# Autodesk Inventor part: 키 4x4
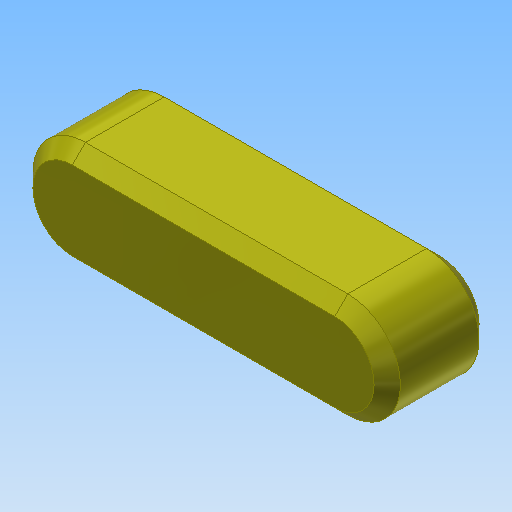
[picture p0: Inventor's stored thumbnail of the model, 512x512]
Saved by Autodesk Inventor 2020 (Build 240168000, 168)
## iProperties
Created: 2016-04
Part Number: 키 4x4
Document SubType Name: Modeling
Designer: mdu
Density: 7.86 g/cm^3
Mass: 1.65269 g
Surface Area: 2.35398 cm^2
Volume: 0.210265 cm^3
Material: 강철, 연강
Appearance: 노란색
Author: mdu
Revision Number: 1
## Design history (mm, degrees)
sketch "스케치1"
  geometry: L1 (-5, -2)-(5, -2); L2 (5, 2)-(-5, 2); A1 r 2 centre (5, 0) between (5, -2) and (5, 2); A2 r 2 centre (-5, 0) between (-5, 2) and (-5, -2); 2 further points
  constraints: 4 end point, 4 point on circle, 4 tangent, 2 centre point, 1 horizontal, 1 horizontal alignment, 1 midpoint, 1 parallel, 1 vertical alignment
  dimensions: "d0" = 4 distance between parallel lines of L1 L2; "d1" = 14 dimension on A1 A2
extrude "돌출1" new body sketch "스케치1" stored distance "d2" = 4; taper "d3" = 0 deg
chamfer "모따기1" distance "d4" = 0.5; stored, may be unused: second distance "d5" = 2, angle "d6" = 45 deg
node "솔리드1"
